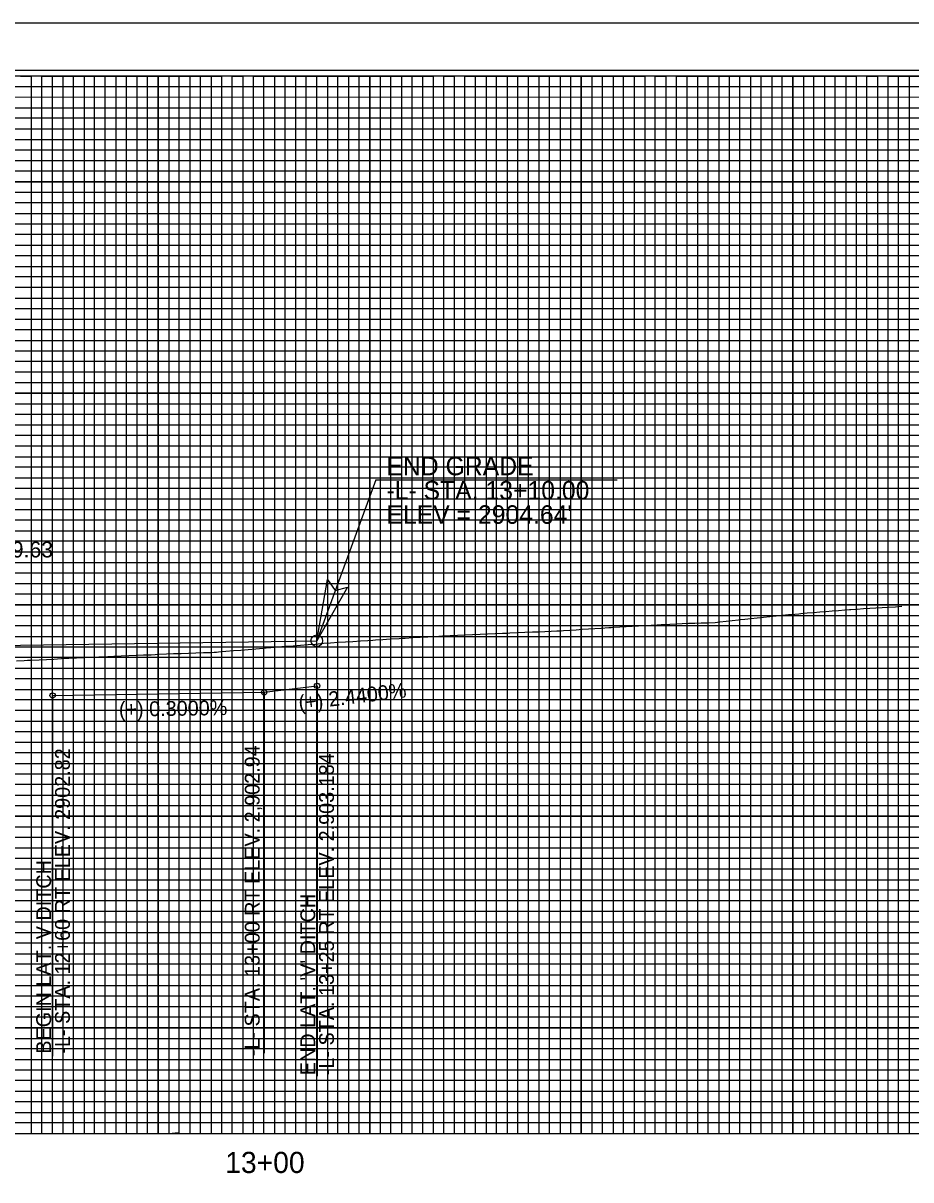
# Model space of a CAD drawing. Extents: x 1191114 to 1192543, y 893004 to 894332.
# Drawn here: x 1191546.9 to 1191714.7, y 894113.5 to 894332.3 of the extents above; entities that cross this region are included whole.
import ezdxf

# ---------------------------------------------------------------- set-up
doc = ezdxf.new("R2010")
doc.units = 0
for name, color, linetype in [('Exist Profile Cell', 7, 'Continuous'), ('Exist Vertical Profile Ground Line', 7, 'Continuous'), ('Prop PFL Text', 7, 'Continuous'), ('Prop Terminator CELL', 7, 'Continuous'), ('Prop Vertical Profile Curve Label', 7, 'Continuous'), ('Prop Vertical Profile Ditch Grade Right', 7, 'Continuous'), ('Prop Vertical Profile Ditch Grade Right Label', 7, 'Continuous'), ('Prop Vertical Profile Grade', 7, 'Continuous'), ('Prop VPI Ditch Grade Right Label', 7, 'Continuous'), ('Prop VPI Label', 7, 'Continuous'), ('Sheet Cutting Line CELL', 7, 'Continuous'), ('Sheet DOT Grid CELL', 7, 'Continuous'), ('Sheet Layout Profile Border Port 1', 7, 'Continuous'), ('Sheet Plot Border Inside CELL', 7, 'Continuous'), ('Sheet Plot Border Outside CELL', 7, 'Continuous'), ('Sheet Profile CELL', 7, 'Continuous'), ('Sheet Profile Grid Major CELL', 7, 'Continuous'), ('Sheet Profile Grid Middle CELL', 7, 'Continuous'), ('Sheet Profile Grid Minor CELL', 7, 'Continuous')]:
    doc.layers.add(name, color=color, linetype=linetype)

msp = doc.modelspace()

# ---------------------------------------------------------------- linework, layer by layer
at = {"layer": 'Exist Profile Cell'}
msp.add_line((1191292.39, 894142.3), (1191713, 894142.3), dxfattribs=at)
at = {"layer": 'Exist Vertical Profile Ground Line'}
msp.add_lwpolyline([(1191545.63, 894211.7), (1191547.04, 894211.77), (1191547.72, 894211.8), (1191548.45, 894211.83), (1191549.87, 894211.9), (1191551.28, 894211.97), (1191552.69, 894212.04), (1191553.35, 894212.08), (1191554.11, 894212.12), (1191555.52, 894212.19), (1191556.93, 894212.25), (1191558.34, 894212.32), (1191559.76, 894212.38), (1191561.17, 894212.45), (1191562.85, 894212.52), (1191564, 894212.57), (1191565.41, 894212.63), (1191566.82, 894212.69), (1191568.24, 894212.75), (1191569.65, 894212.8), (1191571.06, 894212.86), (1191571.81, 894212.89), (1191572.48, 894212.93), (1191573.99, 894213.02), (1191575.3, 894213.06), (1191576.72, 894213.11), (1191578.13, 894213.16), (1191579.54, 894213.21), (1191580.96, 894213.25), (1191582.37, 894213.3), (1191582.99, 894213.32), (1191583.45, 894213.35), (1191583.78, 894213.38), (1191585.2, 894213.5), (1191586.61, 894213.62), (1191588.02, 894213.74), (1191589.44, 894213.86), (1191590.85, 894213.98), (1191592.26, 894214.09), (1191592.79, 894214.14), (1191593.68, 894214.22), (1191595.09, 894214.33), (1191596.5, 894214.44), (1191597.92, 894214.55), (1191599.33, 894214.66), (1191600.74, 894214.77), (1191602.16, 894214.87), (1191602.67, 894214.91), (1191603.68, 894215.01), (1191604.98, 894215.1), (1191606.4, 894215.2), (1191607.81, 894215.29), (1191609.22, 894215.38), (1191610.64, 894215.48), (1191612.05, 894215.57), (1191613.01, 894215.62), (1191613.46, 894215.65), (1191614.88, 894215.75), (1191616.29, 894215.84), (1191617.98, 894215.94), (1191618.48, 894215.96), (1191619.12, 894216), (1191620.53, 894216.09), (1191621.94, 894216.17), (1191623.36, 894216.25), (1191624.77, 894216.32), (1191626.18, 894216.4), (1191627.6, 894216.47), (1191628.05, 894216.5), (1191629.01, 894216.53), (1191630.42, 894216.6), (1191631.84, 894216.67), (1191633.25, 894216.73), (1191634.66, 894216.8), (1191636.08, 894216.86), (1191637.49, 894216.93), (1191638.29, 894216.96), (1191638.9, 894216.99), (1191640.32, 894217.05), (1191641.73, 894217.11), (1191643.14, 894217.16), (1191644.32, 894217.21), (1191645.5, 894217.26), (1191646.69, 894217.3), (1191647.8, 894217.34), (1191648.25, 894217.35), (1191648.62, 894217.38), (1191649.05, 894217.41), (1191650.23, 894217.5), (1191651.41, 894217.58), (1191652.59, 894217.66), (1191653.77, 894217.74), (1191654.95, 894217.82), (1191656.14, 894217.89), (1191657.59, 894217.98), (1191658.06, 894218.03), (1191658.5, 894218.06), (1191659.68, 894218.13), (1191660.86, 894218.2), (1191662.04, 894218.27), (1191663.22, 894218.33), (1191664.4, 894218.4), (1191665.58, 894218.46), (1191666.77, 894218.52), (1191667.52, 894218.55), (1191667.95, 894218.59), (1191669.13, 894218.64), (1191670.31, 894218.7), (1191671.49, 894218.74), (1191672.67, 894218.79), (1191673.85, 894218.83), (1191675.03, 894218.87), (1191676.22, 894218.91), (1191677.68, 894218.96), (1191678.58, 894219.07), (1191679.76, 894219.21), (1191680.94, 894219.35), (1191682.12, 894219.48), (1191682.52, 894219.53), (1191683.3, 894219.6), (1191684.48, 894219.73), (1191685.67, 894219.85), (1191686.85, 894219.97), (1191688.03, 894220.09), (1191689.21, 894220.21), (1191690.39, 894220.32), (1191691.57, 894220.43), (1191692.18, 894220.49), (1191692.75, 894220.54), (1191693.51, 894220.61), (1191693.93, 894220.65), (1191695.11, 894220.75), (1191696.3, 894220.85), (1191697.48, 894220.95), (1191698.66, 894221.05), (1191699.84, 894221.14), (1191701.02, 894221.23), (1191702.2, 894221.32), (1191703.08, 894221.39), (1191703.38, 894221.41), (1191704.56, 894221.49), (1191705.75, 894221.57), (1191706.93, 894221.65), (1191708.11, 894221.72), (1191709.29, 894221.79), (1191710.47, 894221.86), (1191711.83, 894221.93), (1191713, 894222.01)], dxfattribs=at)
at = {"layer": 'Prop Terminator CELL'}
msp.add_lwpolyline([(1191608.17, 894225.65), (1191602.39, 894215.5), (1191604.41, 894227.09), (1191605.83, 894225.01)], close=True, dxfattribs=at)
at = {"layer": 'Prop Vertical Profile Curve Label'}
for q in [(1191602.39, 894215.5), (1191659.17, 894245.91)]:
    msp.add_line((1191613.58, 894245.91), q, dxfattribs=at)
at = {"layer": 'Prop Vertical Profile Ditch Grade Right'}
msp.add_lwpolyline([(1191552.44, 894205.15), (1191592.44, 894205.75), (1191602.44, 894206.97)], dxfattribs=at)
at = {"layer": 'Prop Vertical Profile Grade'}
msp.add_line((1191465.39, 894213.44), (1191602.39, 894215.5), dxfattribs=at)
at = {"layer": 'Prop VPI Ditch Grade Right Label'}
for p, q in [((1191602.44, 894206.97), (1191602.44, 894133.15)), ((1191552.44, 894205.15), (1191552.44, 894136.96)), ((1191592.44, 894205.75), (1191592.44, 894137.47))]:
    msp.add_line(p, q, dxfattribs=at)
for centre in [(1191592.44, 894205.75), (1191602.44, 894206.97), (1191552.44, 894205.15)]:
    msp.add_circle(centre, 0.5, dxfattribs=at)
at = {"layer": 'Prop VPI Label'}
msp.add_circle((1191602.39, 894215.5), 1.1, dxfattribs=at)
at = {"layer": 'Sheet Cutting Line CELL'}
msp.add_line((1191839.19, 894332.3), (1191165.59, 894332.3), dxfattribs=at)
at = {"layer": 'Sheet DOT Grid CELL'}
for p, q in [((1191552.39, 894122.3), (1191552.39, 894322.3)), ((1191572.39, 894122.3), (1191572.39, 894322.3)), ((1191592.39, 894122.3), (1191592.39, 894322.3)), ((1191612.39, 894122.3), (1191612.39, 894322.3)), ((1191632.39, 894122.3), (1191632.39, 894322.3)), ((1191652.39, 894122.3), (1191652.39, 894322.3)), ((1191672.39, 894122.3), (1191672.39, 894322.3)), ((1191692.39, 894122.3), (1191692.39, 894322.3)), ((1191712.39, 894122.3), (1191712.39, 894322.3)), ((1191752.37, 894302.3), (1191232.39, 894302.3)), ((1191752.37, 894282.3), (1191232.39, 894282.3)), ((1191832.39, 894262.3), (1191232.39, 894262.3)), ((1191832.39, 894242.3), (1191232.39, 894242.3)), ((1191832.39, 894222.3), (1191232.39, 894222.3)), ((1191832.39, 894202.3), (1191232.39, 894202.3)), ((1191832.39, 894182.3), (1191232.39, 894182.3)), ((1191832.39, 894162.3), (1191232.39, 894162.3)), ((1191832.39, 894142.3), (1191232.39, 894142.3))]:
    msp.add_line(p, q, dxfattribs=at)
at = {"layer": 'Sheet Layout Profile Border Port 1'}
msp.add_lwpolyline([(1191252.39, 894322.3), (1191252.39, 894122.3), (1191812.39, 894122.3), (1191812.39, 894267.28), (1191752.37, 894267.28), (1191752.37, 894322.3)], close=True, dxfattribs=at)
at = {"layer": 'Sheet Plot Border Inside CELL'}
msp.add_lwpolyline([(1191170.79, 893901.28), (1191837.39, 893901.28), (1191837.39, 894323.32), (1191170.79, 894323.32)], close=True, dxfattribs=at)
at = {"layer": 'Sheet Plot Border Outside CELL'}
msp.add_lwpolyline([(1191165.59, 893892.3), (1191839.19, 893892.3), (1191839.19, 894332.3), (1191165.59, 894332.3)], close=True, dxfattribs=at)
at = {"layer": 'Sheet Profile CELL'}
msp.add_line((1191232.39, 894122.3), (1191832.39, 894122.3), dxfattribs=at)
msp.add_lwpolyline([(1191832.39, 894322.3), (1191232.39, 894322.3), (1191232.39, 893902.3), (1191832.39, 893902.3)], close=True, dxfattribs=at)
at = {"layer": 'Sheet Profile Grid Major CELL'}
for points in [[(1191532.39, 894122.3), (1191552.39, 894122.3), (1191552.39, 894322.3), (1191572.39, 894322.3), (1191572.39, 894122.3), (1191592.39, 894122.3), (1191592.39, 894322.3), (1191612.39, 894322.3), (1191612.39, 894122.3), (1191632.39, 894122.3), (1191632.39, 894322.3), (1191652.39, 894322.3), (1191652.39, 894122.3), (1191672.39, 894122.3), (1191672.39, 894322.3), (1191692.39, 894322.3), (1191692.39, 894122.3), (1191712.39, 894122.3), (1191712.39, 894322.3), (1191732.39, 894322.3), (1191732.39, 894122.3), (1191752.39, 894122.3), (1191752.39, 894322.3), (1191762.91, 894322.3)], [(1191232.39, 894302.3), (1191752.39, 894302.3)], [(1191752.39, 894282.3), (1191232.39, 894282.3), (1191232.39, 894262.3), (1191832.39, 894262.3)], [(1191832.39, 894242.3), (1191232.39, 894242.3), (1191232.39, 894222.3), (1191832.39, 894222.3)], [(1191832.39, 894202.3), (1191232.39, 894202.3), (1191232.39, 894182.3), (1191832.39, 894182.3)], [(1191832.39, 894162.3), (1191232.39, 894162.3), (1191232.39, 894162.3), (1191232.39, 894142.3), (1191832.39, 894142.3)]]:
    msp.add_lwpolyline(points, dxfattribs=at)
at = {"layer": 'Sheet Profile Grid Middle CELL'}
msp.add_line((1191232.39, 894312.3), (1191752.37, 894312.3), dxfattribs=at)
for points in [[(1191542.39, 894122.3), (1191562.39, 894122.3), (1191562.39, 894322.3), (1191582.39, 894322.3), (1191582.39, 894122.3), (1191602.39, 894122.3), (1191602.39, 894322.3), (1191622.39, 894322.3), (1191622.39, 894122.3), (1191642.39, 894122.3), (1191642.39, 894322.3), (1191662.39, 894322.3), (1191662.39, 894122.3), (1191682.39, 894122.3), (1191682.39, 894322.3), (1191702.39, 894322.3), (1191702.39, 894122.3), (1191722.39, 894122.3), (1191722.39, 894322.3), (1191742.39, 894322.3), (1191742.39, 894122.3), (1191762.39, 894122.3), (1191762.39, 894267.28)], [(1191752.39, 894292.3), (1191232.39, 894292.3), (1191232.39, 894272.3), (1191752.39, 894272.3)], [(1191832.39, 894252.3), (1191232.39, 894252.3), (1191232.39, 894232.3), (1191762.39, 894232.3)], [(1191832.39, 894212.3), (1191232.39, 894212.3), (1191232.39, 894192.3), (1191832.39, 894192.3)], [(1191832.39, 894172.3), (1191232.39, 894172.3), (1191232.39, 894152.3), (1191832.39, 894152.3)], [(1191832.39, 894132.3), (1191232.39, 894132.3)]]:
    msp.add_lwpolyline(points, dxfattribs=at)
at = {"layer": 'Sheet Profile Grid Minor CELL'}
for p, q in [((1191252.39, 894320.3), (1191752.39, 894320.3)), ((1191752.39, 894318.3), (1191252.39, 894318.16)), ((1191252.39, 894316.3), (1191752.39, 894316.3)), ((1191752.37, 894268.3), (1191252.39, 894268.3)), ((1191812.39, 894266.3), (1191252.39, 894266.3)), ((1191812.39, 894264.3), (1191252.39, 894264.3)), ((1191252.39, 894260.3), (1191812.39, 894260.3)), ((1191812.39, 894258.3), (1191252.39, 894258.3)), ((1191252.39, 894256.3), (1191812.39, 894256.3)), ((1191812.39, 894248.3), (1191252.39, 894248.3)), ((1191252.39, 894246.3), (1191812.39, 894246.3)), ((1191812.39, 894238.3), (1191252.39, 894238.3)), ((1191252.39, 894236.3), (1191812.39, 894236.3)), ((1191812.39, 894228.3), (1191252.39, 894228.3)), ((1191252.39, 894226.3), (1191812.39, 894226.3)), ((1191812.39, 894224.3), (1191252.39, 894224.3)), ((1191252.39, 894220.3), (1191812.39, 894220.3)), ((1191812.39, 894218.3), (1191252.39, 894218.3)), ((1191252.39, 894216.3), (1191812.39, 894216.3)), ((1191812.39, 894214.3), (1191252.39, 894214.3)), ((1191252.39, 894210.3), (1191812.39, 894210.3)), ((1191812.39, 894208.3), (1191252.39, 894208.3)), ((1191252.39, 894206.3), (1191812.39, 894206.3)), ((1191812.39, 894204.3), (1191252.39, 894204.3)), ((1191252.39, 894200.3), (1191812.39, 894200.3)), ((1191812.39, 894198.3), (1191252.39, 894198.3)), ((1191252.39, 894196.3), (1191812.39, 894196.3)), ((1191812.39, 894194.3), (1191252.39, 894194.3)), ((1191252.39, 894190.3), (1191812.39, 894190.3)), ((1191812.39, 894188.3), (1191252.39, 894188.3)), ((1191252.39, 894186.3), (1191812.39, 894186.3)), ((1191812.39, 894184.3), (1191252.39, 894184.3)), ((1191252.39, 894180.3), (1191812.39, 894180.3)), ((1191812.39, 894178.3), (1191252.39, 894178.3)), ((1191252.39, 894176.3), (1191812.39, 894176.3)), ((1191812.39, 894174.3), (1191252.39, 894174.3)), ((1191252.39, 894170.3), (1191812.39, 894170.3)), ((1191812.39, 894168.3), (1191252.39, 894168.3)), ((1191812.39, 894166.3), (1191252.39, 894166.3)), ((1191812.39, 894164.3), (1191252.39, 894164.3)), ((1191252.39, 894160.3), (1191812.39, 894160.3)), ((1191812.39, 894158.3), (1191252.39, 894158.3)), ((1191252.39, 894156.3), (1191812.39, 894156.3)), ((1191812.39, 894154.3), (1191252.39, 894154.3)), ((1191252.39, 894150.3), (1191812.39, 894150.3)), ((1191812.39, 894148.3), (1191252.39, 894148.3)), ((1191252.39, 894146.3), (1191812.39, 894146.3)), ((1191812.39, 894144.3), (1191252.39, 894144.3)), ((1191252.39, 894140.3), (1191812.39, 894140.3)), ((1191812.39, 894138.3), (1191252.39, 894138.3)), ((1191252.39, 894136.3), (1191812.39, 894136.3)), ((1191812.39, 894134.3), (1191252.39, 894134.3)), ((1191252.39, 894130.3), (1191812.39, 894130.3)), ((1191812.39, 894128.3), (1191252.39, 894128.3)), ((1191252.39, 894126.3), (1191812.39, 894126.3))]:
    msp.add_line(p, q, dxfattribs=at)
for points in [[(1191546.39, 894322.3), (1191548.39, 894322.3), (1191548.39, 894122.3), (1191550.39, 894122.3), (1191550.39, 894322.3), (1191554.39, 894322.3), (1191554.39, 894122.3), (1191556.39, 894122.3), (1191556.39, 894322.3), (1191558.39, 894322.3), (1191558.39, 894122.3), (1191560.39, 894122.3), (1191560.39, 894322.3), (1191564.39, 894322.3), (1191564.39, 894122.3), (1191566.39, 894122.3), (1191566.39, 894322.3), (1191568.39, 894322.3), (1191568.39, 894122.3), (1191570.39, 894122.3), (1191570.39, 894322.3), (1191574.39, 894322.3), (1191574.39, 894122.3), (1191576.27, 894122.52), (1191576.39, 894122.3), (1191576.39, 894322.3), (1191578.39, 894322.3), (1191578.39, 894122.3), (1191580.39, 894122.3), (1191580.39, 894322.3), (1191584.39, 894322.3), (1191584.39, 894122.3), (1191586.39, 894122.3)], [(1191586.39, 894122.3), (1191586.39, 894322.3), (1191588.39, 894322.3), (1191588.39, 894122.3), (1191590.39, 894122.3), (1191590.39, 894322.3), (1191594.39, 894322.3), (1191594.39, 894122.3), (1191596.39, 894122.3), (1191596.39, 894322.3), (1191598.39, 894322.3), (1191598.39, 894122.3), (1191600.39, 894122.3), (1191600.39, 894322.3), (1191604.39, 894322.3), (1191604.39, 894122.3), (1191606.39, 894122.3), (1191606.39, 894322.3), (1191608.39, 894322.3), (1191608.39, 894122.3), (1191610.39, 894122.3), (1191610.39, 894322.3), (1191614.39, 894322.3), (1191614.39, 894122.3), (1191616.39, 894122.3), (1191616.39, 894322.3), (1191618.39, 894322.3), (1191618.39, 894122.3), (1191620.39, 894122.3), (1191620.39, 894322.3), (1191624.39, 894322.3), (1191624.39, 894122.3), (1191626.39, 894122.3), (1191626.39, 894322.3), (1191628.39, 894322.3), (1191628.39, 894122.3), (1191630.39, 894122.3), (1191630.39, 894322.3), (1191634.39, 894322.3), (1191634.39, 894122.3), (1191636.39, 894122.3), (1191636.39, 894322.3), (1191638.39, 894322.3), (1191638.39, 894122.3), (1191640.39, 894122.3), (1191640.39, 894322.3), (1191644.39, 894322.3), (1191644.39, 894122.3), (1191646.39, 894122.3), (1191646.39, 894322.3), (1191648.39, 894322.3), (1191648.39, 894122.3), (1191650.39, 894122.3), (1191650.39, 894322.3), (1191654.39, 894322.3), (1191654.39, 894122.3), (1191656.39, 894122.3), (1191656.39, 894322.3), (1191658.39, 894322.3), (1191658.39, 894122.3), (1191660.39, 894122.3), (1191660.39, 894322.3), (1191664.39, 894322.3), (1191664.39, 894122.3), (1191666.39, 894122.3), (1191666.39, 894322.3), (1191668.39, 894322.3), (1191668.39, 894122.3), (1191670.39, 894122.3), (1191670.39, 894322.3), (1191674.39, 894322.3), (1191674.39, 894122.3), (1191676.39, 894122.3), (1191676.39, 894322.3), (1191678.39, 894322.3), (1191678.39, 894122.3), (1191680.39, 894122.3), (1191680.39, 894322.3), (1191684.39, 894322.3), (1191684.39, 894122.3), (1191686.39, 894122.3), (1191686.39, 894322.3), (1191688.39, 894322.3), (1191688.39, 894122.3), (1191690.39, 894122.3), (1191690.39, 894322.3), (1191694.39, 894322.3), (1191694.39, 894122.3), (1191696.39, 894122.3), (1191696.39, 894322.3), (1191698.39, 894322.3), (1191698.39, 894122.3), (1191700.39, 894122.3), (1191700.39, 894322.3), (1191704.39, 894322.3), (1191704.39, 894122.3), (1191706.39, 894122.3), (1191706.39, 894322.3), (1191708.39, 894322.3), (1191708.39, 894122.3)], [(1191708.39, 894122.3), (1191710.39, 894122.3), (1191710.39, 894322.3), (1191714.39, 894322.3), (1191714.39, 894122.3), (1191716.39, 894122.3)], [(1191752.39, 894314.3), (1191252.39, 894314.3), (1191252.39, 894310.3), (1191752.39, 894310.3)], [(1191752.37, 894308.3), (1191252.39, 894308.3), (1191252.39, 894306.3), (1191752.39, 894306.3)], [(1191752.39, 894304.3), (1191252.39, 894304.3), (1191252.39, 894300.3), (1191752.39, 894300.3)], [(1191752.39, 894298.3), (1191252.39, 894298.3), (1191252.39, 894296.3), (1191752.39, 894296.3)], [(1191752.39, 894294.3), (1191252.39, 894294.3), (1191252.39, 894290.3), (1191752.39, 894290.3)], [(1191752.39, 894288.3), (1191252.39, 894288.3), (1191252.39, 894286.3), (1191752.39, 894286.3)], [(1191752.39, 894284.3), (1191252.39, 894284.3), (1191252.39, 894280.3), (1191752.39, 894280.3)], [(1191752.39, 894278.26), (1191252.43, 894278.26), (1191252.43, 894276.3), (1191752.39, 894276.3)], [(1191752.39, 894274.3), (1191252.39, 894274.3), (1191252.39, 894270.3), (1191752.39, 894270.3)], [(1191812.39, 894254.3), (1191252.39, 894254.3), (1191252.39, 894250.3), (1191812.39, 894250.3)], [(1191812.39, 894244.3), (1191252.39, 894244.3), (1191252.39, 894240.3), (1191812.39, 894240.3)], [(1191812.39, 894234.3), (1191252.39, 894234.3), (1191252.39, 894230.3), (1191812.39, 894230.3)], [(1191812.39, 894124.3), (1191252.39, 894124.3)]]:
    msp.add_lwpolyline(points, dxfattribs=at)

# ---------------------------------------------------------------- texts
at = {"layer": 'Exist Vertical Profile Ground Line'}
msp.add_text('13+00', height=4, dxfattribs=at).set_placement((1191585.07, 894114.83))
at = {"layer": 'Prop PFL Text'}
msp.add_text('-L- STA. 12+09.63', height=3, dxfattribs=at).set_placement((1191519.63, 894231.25))
at = {"layer": 'Prop Vertical Profile Ditch Grade Right Label'}
for s, rotation, p in [('(+) 2.4400%', 6.9557, (1191599.1, 894202.33)), ('(+) 0.3000%', 0.8594, (1191564.99, 894201.14))]:
    msp.add_text(s, height=2.8, rotation=rotation, dxfattribs=at).set_placement(p)
at = {"layer": 'Prop VPI Ditch Grade Right Label'}
for s, p in [('-L- STA. 13+00 RT ELEV. 2,902.94', (1191591.58, 894136.93)), ('-L- STA. 12+60 RT ELEV. 2902.82', (1191555.7, 894137.4)), ('-L- STA. 13+25 RT ELEV. 2,903.184', (1191605.63, 894133.33)), ('BEGIN LAT. V DITCH', (1191552.15, 894137.4)), ("END LAT. 'V' DITCH", (1191602.08, 894133.33))]:
    msp.add_text(s, height=2.8, rotation=90, dxfattribs=at).set_placement(p)
at = {"layer": 'Prop VPI Label'}
for s, p in [('END GRADE', (1191615.55, 894246.79)), ('-L- STA. 13+10.00', (1191615.55, 894242.2)), ("ELEV = 2904.64'", (1191615.55, 894237.61))]:
    msp.add_text(s, height=3.5, rotation=360, dxfattribs=at).set_placement(p)

doc.saveas('drawing.dxf')
